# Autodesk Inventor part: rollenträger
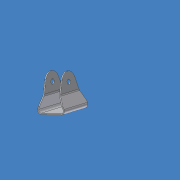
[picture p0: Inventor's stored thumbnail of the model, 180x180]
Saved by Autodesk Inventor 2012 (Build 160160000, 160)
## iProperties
Company: CAD-Verlag
Part Number: rollenträger
Document SubType Name: Sheet Metal
Created: 2004-09
Material: Standard
Designer: Greiling
Manufacturer: Standard
Standards Organization: Custom
Density: 1 g/cm^3
Sheet Metal Rule: Standard
Control State: 0
Master: False
Checked Out: False
Shininess: 64.0
Length Units: 11269
Angle Units: 11279
Time Units: 11290
Mass Units: 11283
Length Display Precision: 3
Angle Display Precision: 2
Compacted: True
Density: 0.0
Volumn: 0.0
Area: 0.0
PropertySet Name: Model Information
Author: Jürgen Kronas
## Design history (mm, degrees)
sketch "Skizze1"
  geometry: L1 (0, 196.114)-(0, -19.083) reference; L2 (-84, 0)-(112, 0) reference; L3 (-84, 0)-(112, 0) reference; L4 (0, -19.083)-(0, 196.114) reference; L5 (0, 0)-(-47.252, 0); L6 (-61.039, 20.909)-(-41.213, 67.17); L7 (-40, 73.079)-(-40, 150); L8 (-40, 150)-(-35, 150); L9 (-35, 150)-(-35, 73.079); L10 (-36.617, 65.2)-(-56.443, 18.939); L11 (-47.252, 5)-(0, 5); L12 (47.252, 5)-(0, 5); L13 (36.617, 65.2)-(56.443, 18.939); L14 (35, 150)-(35, 73.079); L15 (40, 150)-(35, 150); L16 (40, 73.079)-(40, 150); L17 (61.039, 20.909)-(41.213, 67.17); L18 (0, 0)-(47.252, 0); A1 r 20 centre (-55, 73.079) between (-36.617, 65.2) and (-35, 73.079); A2 r 15 centre (-55, 73.079) between (-41.213, 67.17) and (-40, 73.079); A3 r 15 centre (-47.252, 15) between (-61.039, 20.909) and (-47.252, 0); A4 r 10 centre (-47.252, 15) between (-56.443, 18.939) and (-47.252, 5); A5 r 10 centre (47.252, 15) between (47.252, 5) and (56.443, 18.939); A6 r 15 centre (47.252, 15) between (47.252, 0) and (61.039, 20.909); A7 r 15 centre (55, 73.079) between (40, 73.079) and (41.213, 67.17); A8 r 20 centre (55, 73.079) between (35, 73.079) and (36.617, 65.2); 8 further points
  constraints: 28 end point, 20 point on line, 16 point on circle, 16 tangent, 8 centre point, 6 symmetric about line, 4 perpendicular, 1 equal radius, 1 parallel, 7 other
  dimensions: "d0" = 70 distance between parallel lines of L14 L9; "d1" = 5 distance of L7.end L8.end; "d2" = 5 distance of L15.start L14.start (derived); "d3" = 5 distance between parallel lines of L10 L6; "d4" = 5 distance between parallel lines of L5 L11; "d5" = 150 distance between parallel lines of L18 L15; "d6" = 70 distance of L5.start point (-70, 0); "d7" = 80 distance of point (-40, 70) L7.end; "d8" = 20 radius of A1; "d9" = 15 radius of A2; "d10" = 15 radius of A3; "d11" = 10 radius of A4; "d12" = 10 radius of A5; "d13" = 15 radius of A6; "d14" = 20 radius of A8
extrude "Extrusion1" new body sketch "Skizze1" distance "d15" = 140; taper "d16" = 0 deg
workplane "Arbeitsebene2"
sketch "Skizze2"
  geometry: L1 (-15, 0)-(-15, 140) reference; L2 (135, 0)-(135, 140) reference; L3 (135, 140)-(58.079, 140) reference; L4 (58.079, 0)-(135, 0) reference; 1 further point
  dimensions: "d17" = 70 vertical distance of point (95, 70) L1.end; "d18" = 110 distance from line of L1 point (95, 70)
hole "Bohrung1" sketch "Skizze2" at (95, 70) diameter "d19" = 21; stored, may be unused: countersink angle "d23" = 82 deg, drill point angle "d25" = 118 deg; dims "d20" = 6, "d21" = 4, "d22" = 2, "d24" = 8
sketch "Skizze3"
  geometry: L1 (135, 0)-(135, 140) reference; L2 (52.17, 140)-(5.909, 140) reference; L3 (58.079, 140)-(52.17, 140) reference; L4 (-15, 140)-(5.909, 140) reference; L5 (5.909, 0)-(-15, 0) reference; L6 (5.909, 0)-(52.17, 0) reference; L7 (108.077, 107.802)-(15, 140); L8 (-15, 0)-(-15, 140) reference; L9 (15, 0)-(108.077, 32.198); L10 (135, 140)-(58.079, 140) reference; L11 (58.079, 0)-(135, 0) reference; L12 (15, 140)-(135, 140); L13 (135, 0)-(15, 0); C1 r 10.5 at (95, 70) reference; A1 r 40 centre (95, 70) between (108.077, 107.802) and (108.077, 32.198)
  constraints: 8 end point, 2 point on circle, 2 point on line, 2 tangent, 1 centre point, 1 coincident, 1 collinear, 1 parallel
  dimensions: "d26" = 80 diameter of A1; "d27" = 30 distance from line of L8 L7.end; "d28" = 30 distance from line of L8 L9.start
extrude "Extrusion2" cut sketch "Skizze3" stored distance "d29" = 140; taper "d30" = 0 deg
node "Volumenkörper1"
node "Volumenkörpern"
node "Oberflächenkörpern"
other parameters: "Objekthöhe" = 5, "Biegeradius" = 5 (= Objekthöhe), "BreiteBiegungsfreistellung" = 5 (= Objekthöhe), "TiefeBiegungsfreistellung" = 2.5 (= 0.5 x Objekthöhe), "SeamGap" = 0.01, "Übergangsradius" = 5 (= Biegeradius), "JacobiRadiusGröße" = 5 (= Objekthöhe), "Abstandsgröße" = 5 (= Objekthöhe)
